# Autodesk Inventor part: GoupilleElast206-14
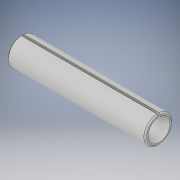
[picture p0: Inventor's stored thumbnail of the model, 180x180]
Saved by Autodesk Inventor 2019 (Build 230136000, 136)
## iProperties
Created: 1999-06
Part Number: GoupilleElast206-14
Material: Générique
Document SubType Name: Modeling
Designer: si-nd67
Density: 1 g/cm^3
Appearance: Par défaut
Author: si-nd67
Sending System: SolidWorks 2014
Last Author: tjost
Last Saved: 2019-02-07
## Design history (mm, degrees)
feature "Enlèv. mat.-Extru.2"
node "Solide1"
